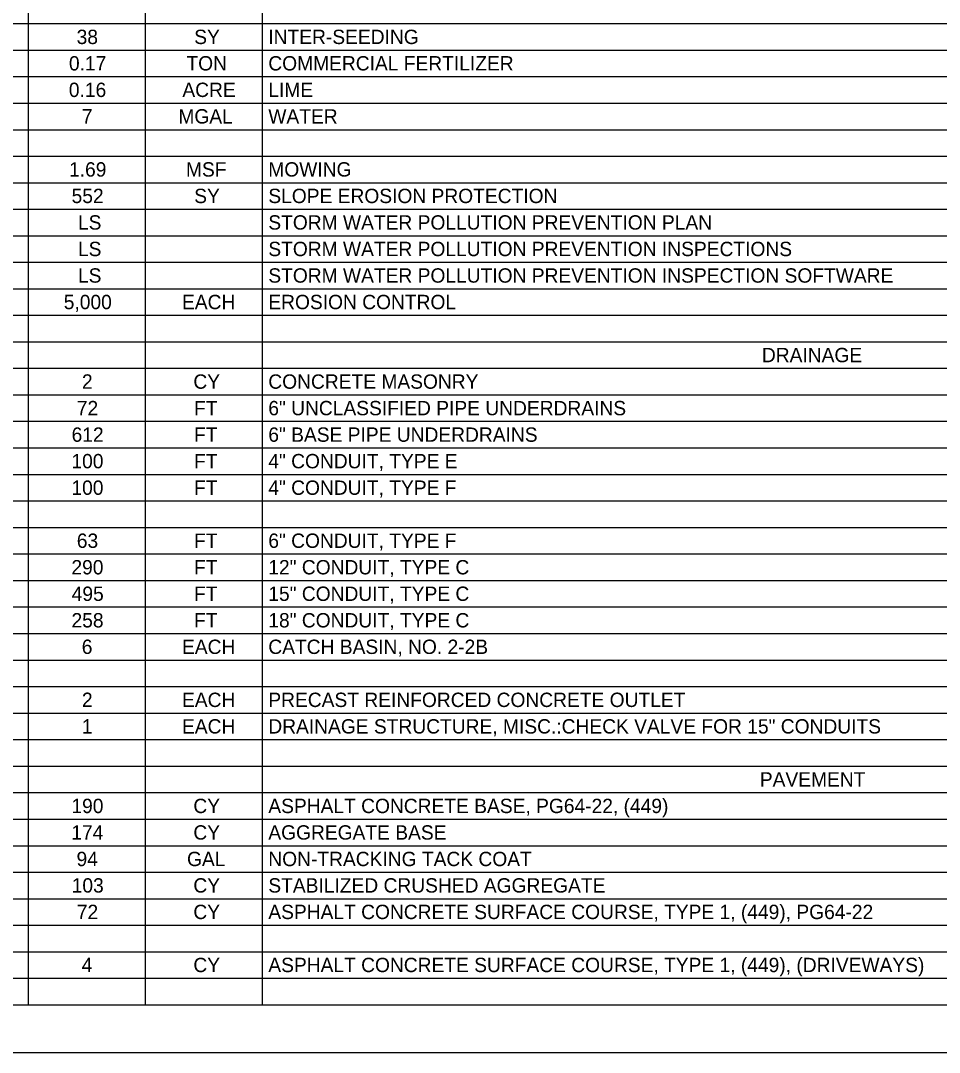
# Model space of a CAD drawing. Extents: x 0 to 34, y 0 to 22.
# Drawn here: x 16.95 to 26.65, y 0 to 10.89 of the extents above; entities that cross this region are included whole.
import ezdxf

# ---------------------------------------------------------------- set-up
doc = ezdxf.new("R2010")
doc.units = 0
for name, color, linetype in [('Default', 7, 'Continuous'), ('SH_Border', 7, 'Continuous'), ('SH_Cut_Line', 7, 'Continuous')]:
    doc.layers.add(name, color=color, linetype=linetype)

msp = doc.modelspace()

# ---------------------------------------------------------------- linework, layer by layer
at = {"layer": 'Default'}
for p, q in [((17.03, 21.5), (17.03, 0.502)), ((18.265, 21.5), (18.265, 0.502)), ((19.5, 21.5), (19.5, 0.502)), ((1.5, 10.861), (32, 10.861)), ((1.5, 10.581), (32, 10.581)), ((1.5, 10.301), (32, 10.301)), ((1.5, 10.021), (32, 10.021)), ((1.5, 9.741), (32, 9.741)), ((1.5, 9.461), (32, 9.461)), ((1.5, 9.181), (32, 9.181)), ((1.5, 8.901), (32, 8.901)), ((1.5, 8.621), (32, 8.621)), ((1.5, 8.342), (32, 8.342)), ((1.5, 8.062), (32, 8.062)), ((1.5, 7.782), (32, 7.782)), ((1.5, 7.502), (32, 7.502)), ((1.5, 7.222), (32, 7.222)), ((1.5, 6.942), (32, 6.942)), ((1.5, 6.662), (32, 6.662)), ((1.5, 6.382), (32, 6.382)), ((1.5, 6.102), (32, 6.102)), ((1.5, 5.822), (32, 5.822)), ((1.5, 5.542), (32, 5.542)), ((1.5, 5.262), (32, 5.262)), ((1.5, 4.982), (32, 4.982)), ((1.5, 4.702), (32, 4.702)), ((1.5, 4.422), (32, 4.422)), ((1.5, 4.142), (32, 4.142)), ((1.5, 3.862), (32, 3.862)), ((1.5, 3.582), (32, 3.582)), ((1.5, 3.302), (32, 3.302)), ((1.5, 3.022), (32, 3.022)), ((1.5, 2.742), (32, 2.742)), ((1.5, 2.462), (32, 2.462)), ((1.5, 2.182), (32, 2.182)), ((1.5, 1.902), (32, 1.902)), ((1.5, 1.622), (32, 1.622)), ((1.5, 1.342), (32, 1.342)), ((1.5, 1.062), (32, 1.062)), ((1.5, 0.782), (32, 0.782)), ((1.5, 0.502), (32, 0.502))]:
    msp.add_line(p, q, dxfattribs=at)
at = {"layer": 'SH_Border'}
msp.add_lwpolyline([(1.5, 21.5), (33.5, 21.5), (33.5, 0.5), (1.5, 0.5)], close=True, dxfattribs=at)
at = {"layer": 'SH_Cut_Line'}
msp.add_lwpolyline([(0, 0), (34, 0), (34, 22), (0, 22)], close=True, dxfattribs=at)

# ---------------------------------------------------------------- texts
at = {"layer": 'Default'}
for s, height, p in [('38', 0.1515, (17.543, 10.645)), ('SY', 0.1515, (18.784, 10.645)), ('INTER-SEEDING', 0.15151, (19.566, 10.645)), ('0.17', 0.1515, (17.462, 10.366)), ('TON', 0.1515, (18.702, 10.366)), ('COMMERCIAL FERTILIZER', 0.15151, (19.566, 10.366)), ('0.16', 0.1515, (17.461, 10.086)), ('ACRE', 0.1515, (18.659, 10.086)), ('LIME', 0.1515, (19.566, 10.086)), ('7', 0.152, (17.598, 9.806)), ('MGAL', 0.1515, (18.617, 9.806)), ('WATER', 0.1515, (19.566, 9.806)), ('1.69', 0.1515, (17.463, 9.246)), ('MSF', 0.1515, (18.697, 9.246)), ('MOWING', 0.1515, (19.566, 9.246)), ('552', 0.1515, (17.49, 8.966)), ('SY', 0.1515, (18.784, 8.966)), ('SLOPE EROSION PROTECTION', 0.15151, (19.566, 8.966)), ('LS', 0.1515, (17.557, 8.686)), ('STORM WATER POLLUTION PREVENTION PLAN', 0.15151, (19.566, 8.686)), ('LS', 0.1515, (17.557, 8.406)), ('STORM WATER POLLUTION PREVENTION INSPECTIONS', 0.15151, (19.566, 8.406)), ('LS', 0.1515, (17.557, 8.126)), ('STORM WATER POLLUTION PREVENTION INSPECTION SOFTWARE', 0.15151, (19.566, 8.126)), ('5,000', 0.1515, (17.407, 7.846)), ('EACH', 0.1515, (18.655, 7.846)), ('EROSION CONTROL', 0.15151, (19.566, 7.846)), ('DRAINAGE', 0.1515, (24.775, 7.286)), ('2', 0.152, (17.599, 7.006)), ('CY', 0.1515, (18.775, 7.006)), ('CONCRETE MASONRY', 0.15151, (19.566, 7.006)), ('72', 0.1515, (17.545, 6.726)), ('FT', 0.1515, (18.782, 6.726)), ('6" UNCLASSIFIED PIPE UNDERDRAINS', 0.15151, (19.566, 6.726)), ('612', 0.1515, (17.49, 6.446)), ('FT', 0.1515, (18.782, 6.446)), ('6" BASE PIPE UNDERDRAINS', 0.15151, (19.566, 6.446)), ('100', 0.1515, (17.488, 6.166)), ('FT', 0.1515, (18.782, 6.166)), ('4" CONDUIT, TYPE E', 0.15151, (19.566, 6.166)), ('100', 0.1515, (17.488, 5.886)), ('FT', 0.1515, (18.782, 5.886)), ('4" CONDUIT, TYPE F', 0.15151, (19.566, 5.886)), ('63', 0.1515, (17.545, 5.326)), ('FT', 0.1515, (18.782, 5.326)), ('6" CONDUIT, TYPE F', 0.15151, (19.566, 5.326)), ('290', 0.1515, (17.488, 5.046)), ('FT', 0.1515, (18.782, 5.046)), ('12" CONDUIT, TYPE C', 0.15151, (19.566, 5.046)), ('495', 0.1515, (17.491, 4.766)), ('FT', 0.1515, (18.782, 4.766)), ('15" CONDUIT, TYPE C', 0.15151, (19.566, 4.766)), ('258', 0.1515, (17.489, 4.486)), ('FT', 0.1515, (18.782, 4.486)), ('18" CONDUIT, TYPE C', 0.15151, (19.566, 4.486)), ('6', 0.152, (17.597, 4.206)), ('EACH', 0.1515, (18.655, 4.206)), ('CATCH BASIN, NO. 2-2B', 0.15151, (19.566, 4.206)), ('2', 0.152, (17.599, 3.646)), ('EACH', 0.1515, (18.655, 3.646)), ('PRECAST REINFORCED CONCRETE OUTLET', 0.15151, (19.566, 3.646)), ('1', 0.152, (17.599, 3.366)), ('EACH', 0.1515, (18.655, 3.366)), ('DRAINAGE STRUCTURE, MISC.:CHECK VALVE FOR 15" CONDUITS', 0.15151, (19.566, 3.366)), ('PAVEMENT', 0.1515, (24.753, 2.806)), ('190', 0.1515, (17.488, 2.526)), ('CY', 0.1515, (18.775, 2.526)), ('ASPHALT CONCRETE BASE, PG64-22, (449)', 0.15151, (19.566, 2.526)), ('174', 0.1515, (17.487, 2.246)), ('CY', 0.1515, (18.775, 2.246)), ('AGGREGATE BASE', 0.15151, (19.566, 2.246)), ('94', 0.1515, (17.542, 1.966)), ('GAL', 0.1515, (18.708, 1.966)), ('NON-TRACKING TACK COAT', 0.15151, (19.566, 1.966)), ('103', 0.1515, (17.491, 1.687)), ('CY', 0.1515, (18.775, 1.687)), ('STABILIZED CRUSHED AGGREGATE', 0.15151, (19.566, 1.687)), ('72', 0.1515, (17.545, 1.407)), ('CY', 0.1515, (18.775, 1.407)), ('ASPHALT CONCRETE SURFACE COURSE, TYPE 1, (449), PG64-22', 0.15151, (19.566, 1.407)), ('4', 0.152, (17.596, 0.847)), ('CY', 0.1515, (18.775, 0.847)), ('ASPHALT CONCRETE SURFACE COURSE, TYPE 1, (449), (DRIVEWAYS)', 0.15151, (19.566, 0.847))]:
    msp.add_text(s, height=height, dxfattribs=at).set_placement(p)

doc.saveas('drawing.dxf')
